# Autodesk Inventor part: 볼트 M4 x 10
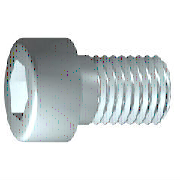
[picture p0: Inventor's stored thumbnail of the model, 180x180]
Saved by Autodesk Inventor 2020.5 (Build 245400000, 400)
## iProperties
Created: 2016-04
Part Number: 볼트 M4 x 10
Material: 강철, 연강
Description: 6각머리 태핑 나사
Document SubType Name: Modeling
Standard: KS B 1003
Designer: mdu
Standards Organization: KS
Language: ko-KR
Size Designation: M 4 x 10
Categories: <MemberInstance><Categories><Category DisplayName="조임쇠" InternalName="e4da775c-781d-43d5-af7c-5136215cf5a6" Mnemonic="FSTN"><Category DisplayName="볼트" InternalN
Density: 7.86 g/cm^3
Mass: 2.0371 g
Surface Area: 3.0572 cm^2
Volume: 0.259174 cm^3
Appearance: 강철
IsCustomPart: 0
Author: mdu
Revision Number: 1
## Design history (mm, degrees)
sketch "스케치1"
  geometry: L1 (-1, 0)-(10, 0); L2 (10, 0)-(10, 2); L3 (10, 2)-(1.75, 2); L4 (1.75, 2)-(1.32, 2); L5 (1.32, 2)-(0, 2); L6 (0, 2)-(0, 3.5); L7 (0, 3.5)-(-4, 3.5); L8 (-4, 3.5)-(-4, 1.732); L9 (-4, 1.732)-(-2, 1.732); L10 (-2, 1.732)-(-1, 0); L11 (-6.8, 0)-(12.8, 0) reference; L12 (0, -0.7)-(0, 4.2) reference; L13 (1.75, 2)-(0, 2)
  constraints: 22 end point, 6 parallel, 2 collinear, 2 perpendicular, 1 horizontal, 1 point on line
  dimensions: "d1" = 8.25 distance from line of L3.end L2 (= GEL); "d2" = 0.42952 distance of L4.end L3.end (computed from GAL); "d3" = 4 distance between parallel lines of L8 L6 (= KOH); "d4" = 2 distance of L8.end L9.end (= INTI); "d5" = 60 deg angle of L10 L1; "d6" = 4 diameter of L3 L1 (= GD); "d7" = 4 diameter of L5 L1 (= BDM); "d8" = 3.4641 diameter of L9 L1 (= 1.1547 x SW); "d9" = 7 diameter of L7 L1 (= KOD); "d26" = 10 distance between parallel lines of L12 L2 (= NLG)
revolve "본체" sketch "스케치1" stored, may be unused: angle "d10" = 90 deg
sketch "스케치2"
  geometry: L1 (0, -4.9)-(0, 4.9) reference; L2 (-4.9, 0)-(4.9, 0) reference; L3 (1.732, 0)-(0.866, -1.5); L4 (0.866, -1.5)-(-0.866, -1.5); L5 (-0.866, -1.5)-(-1.732, 0); L6 (-1.732, 0)-(-0.866, 1.5); L7 (-0.866, 1.5)-(0.866, 1.5); L8 (0.866, 1.5)-(1.732, 0); 2 further points
  constraints: 12 end point, 1 coincident, 1 horizontal alignment, 1 point on line, 12 other
extrude "슬롯" join sketch "스케치2" stored distance "d11" = 10; taper "d12" = 0 deg
workplane "Work Plane1"
fillet "Fillet2" dims "d30" = 0.1 (= R)
body "Solid1"
fillet "모깎기1" dims "d17" = 0.4 (= RR)
feature "스레드" dims "d13" = 8.25 (= GEL), "d14" = 0
chamfer "모따기1" distance "d15" = 0.42941 (= -0.5 x SPD + 0.5 x GD); stored, may be unused: second distance "d16" = 0.42941 (= GUL), angle "d27" = 45 deg
other parameters: "GD" = 4 (= NND) [user parameter; used in 2 equation terms], "NLG" = 10 [user parameter; used in 1 equation term], "GEL" = 8.25 [user parameter; used in 2 equation terms], "KOD" = 7 [user parameter; used in 1 equation term], "KOH" = 4 [user parameter; used in 1 equation term], "INTI" = 2 [user parameter; used in 1 equation term], "GAL" = 0.42941 (= 0.61345 x PTC) [user parameter; used in 1 equation term], "GUL" = 0.42941 (= 0.61345 x PTC) [user parameter; used in 1 equation term], "BDM" = 4 (= NND) [user parameter; used in 1 equation term], "SW" = 3 [user parameter; used in 2 equation terms], "RR" = 0.4 [user parameter; used in 1 equation term], "SPD" = 3.14117 (= NND - 1.2269 x PTC) [user parameter; used in 1 equation term], "d19" = 0, "d28" = 0, "d29" = 0, "R" = 0.1 [user parameter; used in 1 equation term], "PHH" = 0.2 [user parameter], "GD1" = 3.14117 (= THREADDIA - 1.2269 x PTC) [user parameter], "THREADDIA" = 4 [user parameter; used in 1 equation term], "FAWI" = 45 deg [user parameter], "TPU" = 14.28571 (computed from PTC) [user parameter], "PTC" = 0.7 [user parameter; used in 5 equation terms], "NND" = 4 [user parameter; used in 3 equation terms], "TOA" = 30 deg [user parameter], "E0" = 3.465 (= 1.155 x SW) [user parameter]
